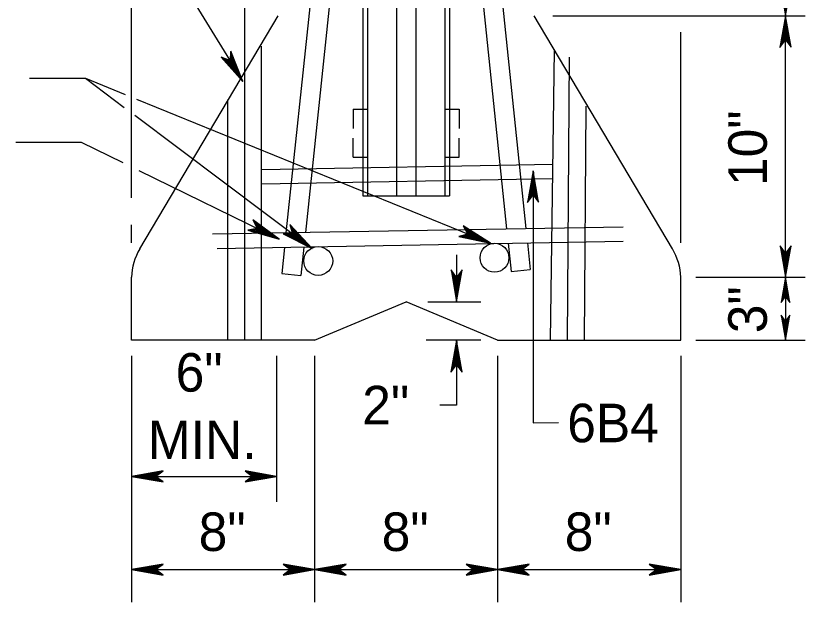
# Model space of a CAD drawing. Extents: x 499883 to 500983, y 499104 to 499764.
# Drawn here: x 500324 to 500405.9, y 499417.1 to 499478 of the extents above; entities that cross this region are included whole.
import ezdxf

# ---------------------------------------------------------------- set-up
doc = ezdxf.new("R2010")
doc.units = 0
for name, color, linetype in [('24', 7, 'Continuous'), ('5', 7, 'Continuous'), ('60', 7, 'Continuous')]:
    doc.layers.add(name, color=color, linetype=linetype)

msp = doc.modelspace()

# ---------------------------------------------------------------- linework, layer by layer
at = {"layer": '24'}
for points in [[(500403.264, 499481.232), (500403.834, 499477.975), (500403.828, 499478.192)], [(500403.834, 499477.975), (500404.412, 499481.249)], [(500403.834, 499477.975), (500403.255, 499474.701), (500403.834, 499475.483), (500404.403, 499474.718), (500403.834, 499477.975), (500403.84, 499477.758), (500403.298, 499474.793), (500403.841, 499475.544), (500404.359, 499474.85), (500403.85, 499477.64), (500403.834, 499477.531), (500403.382, 499474.992), (500403.84, 499475.561), (500404.285, 499474.975), (500403.833, 499477.481), (500403.85, 499477.373), (500403.449, 499475.152), (500403.833, 499475.584), (500404.233, 499475.144), (500403.85, 499477.057), (500403.85, 499476.872), (500403.532, 499475.317), (500403.824, 499475.62), (500404.15, 499475.294), (500403.834, 499476.839), (500403.824, 499476.664), (500403.623, 499475.495), (500403.85, 499475.72), (500404.074, 499475.476), (500403.834, 499476.503), (500403.817, 499476.338), (500403.683, 499475.636), (500403.841, 499475.752), (500404.016, 499475.561), (500403.833, 499476.253), (500403.725, 499475.795), (500403.85, 499475.861), (500403.975, 499475.66), (500403.85, 499476.138), (500403.775, 499475.837), (500403.874, 499475.963), (500403.933, 499475.819), (500403.841, 499475.962), (500403.824, 499475.887)], [(500377.672, 499461.885), (500377.063, 499458.617), (500377.649, 499459.394), (500378.212, 499458.623), (500377.672, 499461.885), (500377.676, 499461.668), (500377.107, 499458.708), (500377.657, 499459.455), (500378.168, 499458.756), (500377.685, 499461.551), (500377.668, 499461.441), (500377.193, 499458.906), (500377.657, 499459.471), (500378.096, 499458.882), (500377.667, 499461.392), (500377.683, 499461.283), (500377.262, 499459.066), (500377.65, 499459.495), (500378.045, 499459.05), (500377.68, 499460.967), (500377.678, 499460.782), (500377.346, 499459.23), (500377.641, 499459.53), (500377.964, 499459.201), (500377.662, 499460.749), (500377.65, 499460.574), (500377.439, 499459.407), (500377.668, 499459.63), (500377.89, 499459.384), (500377.659, 499460.414), (500377.641, 499460.249), (500377.5, 499459.548), (500377.659, 499459.662), (500377.832, 499459.469), (500377.656, 499460.163), (500377.543, 499459.707), (500377.669, 499459.771), (500377.792, 499459.569), (500377.672, 499460.048), (500377.594, 499459.748), (500377.694, 499459.873), (500377.751, 499459.728), (500377.661, 499459.873), (500377.643, 499459.797)], [(500377.672, 499461.885), (500377.646, 499435.755), (500380.277, 499435.775)], [(500403.834, 499450.84), (500404.412, 499454.114), (500403.834, 499453.332), (500403.264, 499454.097), (500403.834, 499450.84), (500403.828, 499451.058), (500404.37, 499454.022), (500403.827, 499453.271), (500403.309, 499453.965), (500403.818, 499451.175), (500403.834, 499451.284), (500404.285, 499453.824), (500403.827, 499453.254), (500403.383, 499453.84), (500403.834, 499451.334), (500403.818, 499451.443), (500404.218, 499453.663), (500403.834, 499453.231), (500403.434, 499453.672), (500403.817, 499451.759), (500403.818, 499451.943), (500404.136, 499453.498), (500403.843, 499453.196), (500403.517, 499453.521), (500403.834, 499451.977), (500403.844, 499452.151), (500404.044, 499453.32), (500403.817, 499453.095), (500403.593, 499453.339), (500403.834, 499452.312), (500403.85, 499452.477), (500403.985, 499453.179), (500403.827, 499453.063), (500403.652, 499453.254), (500403.834, 499452.563), (500403.943, 499453.02), (500403.818, 499452.954), (500403.692, 499453.155), (500403.817, 499452.678), (500403.892, 499452.978), (500403.794, 499452.852), (500403.735, 499452.997), (500403.827, 499452.853), (500403.843, 499452.928)], [(500403.834, 499450.84), (500403.371, 499448.221), (500403.834, 499448.847), (500404.29, 499448.235), (500403.834, 499450.84), (500403.838, 499450.666), (500403.405, 499448.295), (500403.839, 499448.896), (500404.253, 499448.34), (500403.847, 499450.573), (500403.834, 499450.485), (500403.472, 499448.454), (500403.839, 499448.909), (500404.195, 499448.441), (500403.833, 499450.445), (500403.847, 499450.358), (500403.526, 499448.583), (500403.833, 499448.928), (500404.153, 499448.575), (500403.847, 499450.106), (500403.847, 499449.958), (500403.592, 499448.714), (500403.826, 499448.956), (500404.086, 499448.695), (500403.834, 499449.931), (500403.826, 499449.792), (500403.666, 499448.856), (500403.847, 499449.036), (500404.026, 499448.841), (500403.834, 499449.663), (500403.82, 499449.531), (500403.713, 499448.969), (500403.839, 499449.062), (500403.979, 499448.909), (500403.833, 499449.463), (500403.746, 499449.096), (500403.847, 499449.149), (500403.947, 499448.989), (500403.847, 499449.37), (500403.787, 499449.13), (500403.866, 499449.231), (500403.913, 499449.115), (500403.839, 499449.23), (500403.826, 499449.17)], [(500403.834, 499444.305), (500404.297, 499446.924), (500403.834, 499446.298), (500403.378, 499446.91), (500403.834, 499444.305), (500403.829, 499444.479), (500404.263, 499446.85), (500403.828, 499446.249), (500403.414, 499446.805), (500403.821, 499444.572), (500403.834, 499444.66), (500404.195, 499446.691), (500403.828, 499446.236), (500403.473, 499446.704), (500403.834, 499444.699), (500403.821, 499444.786), (500404.141, 499446.563), (500403.834, 499446.217), (500403.515, 499446.57), (500403.82, 499445.039), (500403.821, 499445.187), (500404.076, 499446.431), (500403.841, 499446.189), (500403.581, 499446.449), (500403.834, 499445.213), (500403.842, 499445.353), (500404.002, 499446.288), (500403.82, 499446.108), (500403.641, 499446.304), (500403.834, 499445.482), (500403.847, 499445.614), (500403.954, 499446.175), (500403.828, 499446.083), (500403.688, 499446.236), (500403.834, 499445.682), (500403.921, 499446.049), (500403.821, 499445.996), (500403.72, 499446.156), (500403.82, 499445.774), (500403.881, 499446.015), (500403.802, 499445.914), (500403.754, 499446.03), (500403.828, 499445.915), (500403.841, 499445.975)], [(500336.003, 499430.184), (500339.277, 499429.605), (500338.495, 499430.184), (500339.261, 499430.753), (500336.003, 499430.184), (500336.221, 499430.189), (500339.186, 499429.648), (500338.434, 499430.191), (500339.128, 499430.709), (500336.338, 499430.2), (500336.447, 499430.184), (500338.987, 499429.732), (500338.417, 499430.19), (500339.003, 499430.635), (500336.497, 499430.183), (500336.606, 499430.2), (500338.826, 499429.799), (500338.394, 499430.183), (500338.835, 499430.583), (500336.922, 499430.2), (500337.107, 499430.2), (500338.661, 499429.882), (500338.359, 499430.174), (500338.684, 499430.5), (500337.14, 499430.184), (500337.314, 499430.173), (500338.483, 499429.973), (500338.259, 499430.2), (500338.502, 499430.424), (500337.475, 499430.184), (500337.64, 499430.167), (500338.342, 499430.033), (500338.226, 499430.191), (500338.418, 499430.366), (500337.725, 499430.183), (500338.183, 499430.075), (500338.117, 499430.2), (500338.318, 499430.325), (500337.841, 499430.2), (500338.141, 499430.125), (500338.015, 499430.224), (500338.16, 499430.283), (500338.016, 499430.191), (500338.091, 499430.174)], [(500351.043, 499430.184), (500347.769, 499430.762), (500348.551, 499430.184), (500347.786, 499429.614), (500351.043, 499430.184), (500350.826, 499430.178), (500347.861, 499430.719), (500348.612, 499430.177), (500347.918, 499429.659), (500350.708, 499430.167), (500350.599, 499430.184), (500348.059, 499430.635), (500348.629, 499430.177), (500348.043, 499429.732), (500350.549, 499430.184), (500350.44, 499430.167), (500348.22, 499430.568), (500348.652, 499430.184), (500348.211, 499429.784), (500350.124, 499430.167), (500349.94, 499430.167), (500348.385, 499430.486), (500348.687, 499430.193), (500348.362, 499429.868), (500349.907, 499430.184), (500349.732, 499430.194), (500348.563, 499430.394), (500348.788, 499430.167), (500348.544, 499429.943), (500349.571, 499430.184), (500349.406, 499430.2), (500348.704, 499430.334), (500348.82, 499430.177), (500348.629, 499430.002), (500349.321, 499430.184), (500348.863, 499430.293), (500348.929, 499430.167), (500348.728, 499430.042), (500349.205, 499430.167), (500348.905, 499430.242), (500349.031, 499430.144), (500348.887, 499430.084), (500349.03, 499430.177), (500348.955, 499430.193)], [(500336.003, 499420.505), (500339.277, 499419.926), (500338.495, 499420.505), (500339.261, 499421.075), (500336.003, 499420.505), (500336.221, 499420.511), (500339.186, 499419.969), (500338.434, 499420.512), (500339.128, 499421.03), (500336.338, 499420.521), (500336.447, 499420.505), (500338.987, 499420.053), (500338.417, 499420.512), (500339.003, 499420.956), (500336.497, 499420.504), (500336.606, 499420.521), (500338.826, 499420.12), (500338.394, 499420.504), (500338.835, 499420.904), (500336.922, 499420.521), (500337.107, 499420.521), (500338.661, 499420.203), (500338.359, 499420.496), (500338.684, 499420.821), (500337.14, 499420.505), (500337.314, 499420.495), (500338.483, 499420.295), (500338.259, 499420.521), (500338.502, 499420.746), (500337.475, 499420.505), (500337.64, 499420.488), (500338.342, 499420.354), (500338.226, 499420.512), (500338.418, 499420.687), (500337.725, 499420.504), (500338.183, 499420.396), (500338.117, 499420.521), (500338.318, 499420.646), (500337.841, 499420.521), (500338.141, 499420.446), (500338.015, 499420.545), (500338.16, 499420.604), (500338.016, 499420.512), (500338.091, 499420.496)], [(500354.989, 499420.505), (500351.715, 499421.084), (500352.497, 499420.505), (500351.732, 499419.935), (500354.989, 499420.505), (500354.771, 499420.499), (500351.807, 499421.041), (500352.558, 499420.498), (500351.864, 499419.98), (500354.654, 499420.489), (500354.545, 499420.505), (500352.005, 499420.957), (500352.575, 499420.498), (500351.989, 499420.054), (500354.495, 499420.505), (500354.387, 499420.489), (500352.166, 499420.89), (500352.598, 499420.505), (500352.157, 499420.106), (500354.07, 499420.488), (500353.886, 499420.489), (500352.331, 499420.807), (500352.633, 499420.514), (500352.308, 499420.189), (500353.853, 499420.505), (500353.678, 499420.515), (500352.509, 499420.715), (500352.734, 499420.488), (500352.49, 499420.264), (500353.517, 499420.505), (500353.352, 499420.521), (500352.65, 499420.656), (500352.766, 499420.498), (500352.575, 499420.323), (500353.267, 499420.505), (500352.809, 499420.614), (500352.875, 499420.489), (500352.674, 499420.363), (500353.151, 499420.488), (500352.851, 499420.563), (500352.977, 499420.465), (500352.832, 499420.406), (500352.976, 499420.498), (500352.901, 499420.514)], [(500354.989, 499420.505), (500358.263, 499419.926), (500357.481, 499420.505), (500358.246, 499421.075), (500354.989, 499420.505), (500355.206, 499420.511), (500358.171, 499419.969), (500357.42, 499420.512), (500358.114, 499421.03), (500355.324, 499420.521), (500355.433, 499420.505), (500357.972, 499420.053), (500357.403, 499420.512), (500357.989, 499420.956), (500355.483, 499420.504), (500355.591, 499420.521), (500357.811, 499420.12), (500357.379, 499420.504), (500357.82, 499420.904), (500355.907, 499420.521), (500356.092, 499420.521), (500357.647, 499420.203), (500357.344, 499420.496), (500357.67, 499420.821), (500356.125, 499420.505), (500356.3, 499420.495), (500357.469, 499420.295), (500357.244, 499420.521), (500357.488, 499420.746), (500356.46, 499420.505), (500356.625, 499420.488), (500357.328, 499420.354), (500357.212, 499420.512), (500357.403, 499420.687), (500356.711, 499420.504), (500357.169, 499420.396), (500357.103, 499420.521), (500357.304, 499420.646), (500356.826, 499420.521), (500357.127, 499420.446), (500357.001, 499420.545), (500357.145, 499420.604), (500357.001, 499420.512), (500357.077, 499420.496)], [(500373.974, 499420.505), (500370.7, 499421.084), (500371.483, 499420.505), (500370.717, 499419.935), (500373.974, 499420.505), (500373.757, 499420.499), (500370.792, 499421.041), (500371.544, 499420.498), (500370.849, 499419.98), (500373.64, 499420.489), (500373.531, 499420.505), (500370.991, 499420.957), (500371.56, 499420.498), (500370.975, 499420.054), (500373.481, 499420.505), (500373.372, 499420.489), (500371.152, 499420.89), (500371.584, 499420.505), (500371.143, 499420.106), (500373.056, 499420.488), (500372.871, 499420.489), (500371.316, 499420.807), (500371.619, 499420.514), (500371.293, 499420.189), (500372.838, 499420.505), (500372.663, 499420.515), (500371.495, 499420.715), (500371.719, 499420.488), (500371.475, 499420.264), (500372.503, 499420.505), (500372.338, 499420.521), (500371.636, 499420.656), (500371.751, 499420.498), (500371.56, 499420.323), (500372.252, 499420.505), (500371.794, 499420.614), (500371.861, 499420.489), (500371.66, 499420.363), (500372.137, 499420.488), (500371.836, 499420.563), (500371.962, 499420.465), (500371.818, 499420.406), (500371.962, 499420.498), (500371.887, 499420.514)], [(500373.974, 499420.505), (500377.248, 499419.926), (500376.466, 499420.505), (500377.231, 499421.075), (500373.974, 499420.505), (500374.192, 499420.511), (500377.157, 499419.969), (500376.405, 499420.512), (500377.099, 499421.03), (500374.309, 499420.521), (500374.418, 499420.505), (500376.958, 499420.053), (500376.388, 499420.512), (500376.974, 499420.956), (500374.468, 499420.504), (500374.577, 499420.521), (500376.797, 499420.12), (500376.365, 499420.504), (500376.806, 499420.904), (500374.893, 499420.521), (500375.078, 499420.521), (500376.632, 499420.203), (500376.33, 499420.496), (500376.655, 499420.821), (500375.111, 499420.505), (500375.285, 499420.495), (500376.454, 499420.295), (500376.229, 499420.521), (500376.473, 499420.746), (500375.446, 499420.505), (500375.611, 499420.488), (500376.313, 499420.354), (500376.197, 499420.512), (500376.389, 499420.687), (500375.696, 499420.504), (500376.154, 499420.396), (500376.088, 499420.521), (500376.289, 499420.646), (500375.812, 499420.521), (500376.112, 499420.446), (500375.986, 499420.545), (500376.131, 499420.604), (500375.987, 499420.512), (500376.062, 499420.496)], [(500392.96, 499420.505), (500389.686, 499421.084), (500390.468, 499420.505), (500389.703, 499419.935), (500392.96, 499420.505), (500392.743, 499420.499), (500389.778, 499421.041), (500390.529, 499420.498), (500389.835, 499419.98), (500392.625, 499420.489), (500392.516, 499420.505), (500389.977, 499420.957), (500390.546, 499420.498), (500389.96, 499420.054), (500392.466, 499420.505), (500392.358, 499420.489), (500390.138, 499420.89), (500390.57, 499420.505), (500390.129, 499420.106), (500392.042, 499420.488), (500391.857, 499420.489), (500390.302, 499420.807), (500390.605, 499420.514), (500390.279, 499420.189), (500391.824, 499420.505), (500391.649, 499420.515), (500390.48, 499420.715), (500390.705, 499420.488), (500390.461, 499420.264), (500391.489, 499420.505), (500391.324, 499420.521), (500390.621, 499420.656), (500390.737, 499420.498), (500390.546, 499420.323), (500391.238, 499420.505), (500390.78, 499420.614), (500390.846, 499420.489), (500390.645, 499420.363), (500391.123, 499420.488), (500390.822, 499420.563), (500390.948, 499420.465), (500390.804, 499420.406), (500390.948, 499420.498), (500390.872, 499420.514)]]:
    msp.add_lwpolyline(points, dxfattribs=at)
at = {"layer": '5'}
for p, q in [((500403.834, 499477.975), (500403.834, 499526.242)), ((500358.258, 499514.732), (500352.017, 499455.451)), ((500368.792, 499514.441), (500374.899, 499455.866)), ((500370.749, 499514.732), (500376.902, 499455.918)), ((500360.485, 499509.168), (500360.485, 499459.293)), ((500363.483, 499509.168), (500363.483, 499459.293)), ((500365.481, 499509.199), (500365.481, 499459.293)), ((500368.479, 499509.199), (500368.479, 499459.293)), ((500368.978, 499509.199), (500368.978, 499459.293)), ((500358.61, 499498.82), (500354.029, 499455.472)), ((500359.985, 499498.127), (500359.985, 499459.293)), ((500347.745, 499444.305), (500347.745, 499497.261)), ((500336.003, 499459.079), (500336.003, 499487.137)), ((500336.853, 499453.78), (500351.219, 499477.975)), ((500392.11, 499453.78), (500377.744, 499477.975)), ((500379.709, 499477.975), (500405.877, 499477.975)), ((500403.834, 499450.84), (500403.834, 499477.975)), ((500392.96, 499454.419), (500392.96, 499476.283)), ((500349.493, 499444.305), (500349.493, 499474.811)), ((500379.47, 499444.305), (500379.856, 499474.397)), ((500381.219, 499444.317), (500381.436, 499473.672)), ((500331.205, 499471.5), (500335.343, 499469.814)), ((500336.521, 499469.334), (500373.236, 499454.373)), ((500345.995, 499444.305), (500345.995, 499469.242)), ((500382.968, 499444.305), (500383.147, 499468.582)), ((500336.335, 499467.646), (500354.718, 499453.838)), ((500358.986, 499468.286), (500358.986, 499466.288)), ((500358.986, 499468.286), (500360.485, 499468.286)), ((500368.479, 499468.286), (500369.977, 499468.286)), ((500369.977, 499468.286), (500369.977, 499466.288)), ((500358.986, 499463.29), (500358.986, 499465.288)), ((500369.977, 499463.29), (500369.977, 499465.288)), ((500358.986, 499463.29), (500360.485, 499463.29)), ((500368.479, 499463.29), (500369.977, 499463.29)), ((500336.756, 499461.931), (500351.292, 499454.801)), ((500349.494, 499462.042), (500379.683, 499462.578)), ((500349.52, 499460.543), (500379.71, 499461.079)), ((500359.985, 499459.293), (500368.978, 499459.293)), ((500336.003, 499454.419), (500336.003, 499456.277)), ((500344.407, 499455.336), (500386.979, 499456.092)), ((500344.867, 499453.845), (500387.006, 499454.593)), ((500351.857, 499453.937), (500351.574, 499451.251)), ((500353.869, 499453.962), (500353.56, 499451.041)), ((500375.055, 499454.378), (500375.361, 499451.443)), ((500377.06, 499454.402), (500377.348, 499451.652)), ((500369.721, 499453.158), (500369.721, 499448.301)), ((500351.573, 499451.251), (500353.56, 499451.041)), ((500375.361, 499451.443), (500377.348, 499451.652)), ((500336.003, 499444.305), (500336.003, 499450.84)), ((500392.96, 499444.305), (500392.96, 499450.84)), ((500394.542, 499450.84), (500405.877, 499450.84)), ((500403.834, 499450.84), (500403.834, 499444.305)), ((500354.989, 499444.305), (500364.482, 499448.301)), ((500373.974, 499444.305), (500364.482, 499448.301)), ((500366.715, 499448.301), (500372.219, 499448.301)), ((500354.989, 499444.305), (500336.003, 499444.305)), ((500372.219, 499444.305), (500366.562, 499444.305)), ((500373.974, 499444.305), (500392.96, 499444.305)), ((500394.542, 499444.305), (500405.877, 499444.305)), ((500336.003, 499442.685), (500336.003, 499417.126)), ((500351.043, 499442.685), (500351.043, 499427.536)), ((500354.989, 499442.685), (500354.989, 499417.126)), ((500373.974, 499442.685), (500373.974, 499417.126)), ((500392.96, 499442.685), (500392.96, 499417.126)), ((500336.003, 499430.184), (500351.043, 499430.184)), ((500336.003, 499420.505), (500354.989, 499420.505)), ((500354.989, 499420.505), (500373.974, 499420.505)), ((500373.974, 499420.505), (500392.96, 499420.505))]:
    msp.add_line(p, q, dxfattribs=at)
for points in [[(500326.216, 499494.065), (500333.475, 499494.065), (500347.528, 499471.164)], [(500347.528, 499471.164), (500346.29, 499474.304), (500346.204, 499473.32), (500345.306, 499473.68), (500347.528, 499471.164), (500347.407, 499471.349), (500346.302, 499474.202), (500346.231, 499473.263), (500345.414, 499473.589), (500347.336, 499471.445), (500347.292, 499471.548), (500346.334, 499473.985), (500346.241, 499473.249), (500345.544, 499473.52), (500347.266, 499471.591), (500347.194, 499471.676), (500346.362, 499473.811), (500346.259, 499473.232), (500345.679, 499473.402), (500347.025, 499471.95), (500346.928, 499472.11), (500346.378, 499473.624), (500346.285, 499473.207), (500345.83, 499473.315), (500346.924, 499472.146), (500346.84, 499472.304), (500346.393, 499473.421), (500346.316, 499473.106), (500345.993, 499473.198), (500346.746, 499472.437), (500346.673, 499472.589), (500346.416, 499473.268), (500346.341, 499473.084), (500346.088, 499473.156), (500346.614, 499472.654), (500346.464, 499473.108), (500346.391, 499472.984), (500346.176, 499473.091), (500346.538, 499472.745), (500346.443, 499473.045), (500346.424, 499472.883), (500346.297, 499472.977), (500346.453, 499472.901), (500346.427, 499472.975)], [(500325.409, 499471.5), (500331.205, 499471.5), (500335.232, 499468.475)], [(500323.989, 499464.863), (500330.777, 499464.863), (500335.088, 499462.749)], [(500351.292, 499454.801), (500348.567, 499456.792), (500349.021, 499455.915), (500348.069, 499455.738), (500351.292, 499454.801), (500351.091, 499454.893), (500348.631, 499456.712), (500349.074, 499455.881), (500348.209, 499455.72), (500350.98, 499454.936), (500350.888, 499455), (500348.774, 499456.547), (500349.089, 499455.874), (500348.356, 499455.731), (500350.842, 499455.022), (500350.736, 499455.056), (500348.891, 499456.414), (500349.113, 499455.87), (500348.533, 499455.703), (500350.448, 499455.197), (500350.279, 499455.28), (500349.005, 499456.265), (500349.149, 499455.863), (500348.707, 499455.711), (500350.257, 499455.309), (500350.101, 499455.396), (500349.125, 499456.102), (500349.229, 499455.794), (500348.907, 499455.699), (500349.951, 499455.459), (500349.808, 499455.548), (500349.228, 499455.984), (500349.263, 499455.788), (500349.01, 499455.715), (500349.723, 499455.571), (500349.354, 499455.875), (500349.358, 499455.731), (500349.119, 499455.707), (500349.61, 499455.607), (500349.37, 499455.811), (500349.44, 499455.664), (500349.282, 499455.675), (500349.454, 499455.695), (500349.393, 499455.743)], [(500354.718, 499453.838), (500352.413, 499456.304), (500352.695, 499455.357), (500351.726, 499455.362), (500354.718, 499453.838), (500354.537, 499453.965), (500352.461, 499456.213), (500352.74, 499455.314), (500351.861, 499455.317), (500354.436, 499454.029), (500354.357, 499454.108), (500352.571, 499456.023), (500352.754, 499455.304), (500352.007, 499455.301), (500354.317, 499454.139), (500354.219, 499454.192), (500352.661, 499455.871), (500352.777, 499455.296), (500352.176, 499455.24), (500353.962, 499454.384), (500353.812, 499454.498), (500352.745, 499455.704), (500352.811, 499455.282), (500352.348, 499455.216), (500353.795, 499454.53), (500353.659, 499454.646), (500352.832, 499455.521), (500352.877, 499455.199), (500352.542, 499455.166), (500353.523, 499454.735), (500353.399, 499454.849), (500352.911, 499455.386), (500352.909, 499455.188), (500352.647, 499455.162), (500353.32, 499454.888), (500353.015, 499455.255), (500352.992, 499455.114), (500352.752, 499455.134), (500353.216, 499454.945), (500353.018, 499455.189), (500353.06, 499455.032), (500352.907, 499455.072), (500353.08, 499455.059), (500353.028, 499455.118)], [(500373.236, 499454.373), (500370.38, 499456.171), (500370.893, 499455.328), (500369.956, 499455.085), (500373.236, 499454.373), (500373.029, 499454.451), (500370.45, 499456.096), (500370.948, 499455.297), (500370.097, 499455.077), (500372.915, 499454.486), (500372.819, 499454.543), (500370.604, 499455.94), (500370.964, 499455.292), (500370.243, 499455.098), (500372.772, 499454.563), (500372.664, 499454.589), (500370.73, 499455.816), (500370.989, 499455.289), (500370.421, 499455.083), (500372.366, 499454.709), (500372.193, 499454.78), (500370.853, 499455.675), (500371.025, 499455.284), (500370.594, 499455.103), (500372.168, 499454.809), (500372.007, 499454.885), (500370.985, 499455.521), (500371.109, 499455.221), (500370.795, 499455.104), (500371.853, 499454.937), (500371.704, 499455.016), (500371.095, 499455.411), (500371.143, 499455.218), (500370.897, 499455.127), (500371.617, 499455.033), (500371.229, 499455.311), (500371.243, 499455.167), (500371.006, 499455.126), (500371.502, 499455.061), (500371.249, 499455.247), (500371.329, 499455.106), (500371.171, 499455.106), (500371.341, 499455.138), (500371.277, 499455.182)], [(500369.721, 499448.301), (500370.308, 499451.625), (500369.721, 499450.831), (500369.142, 499451.608), (500369.721, 499448.301), (500369.715, 499448.522), (500370.265, 499451.532), (500369.714, 499450.769), (500369.188, 499451.474), (500369.704, 499448.641), (500369.721, 499448.752), (500370.179, 499451.331), (500369.714, 499450.752), (500369.263, 499451.347), (500369.721, 499448.803), (500369.704, 499448.913), (500370.111, 499451.167), (500369.721, 499450.729), (500369.316, 499451.176), (500369.704, 499449.234), (500369.704, 499449.421), (500370.027, 499451), (500369.73, 499450.693), (500369.4, 499451.023), (500369.721, 499449.455), (500369.731, 499449.632), (500369.934, 499450.819), (500369.704, 499450.591), (500369.477, 499450.838), (500369.721, 499449.795), (500369.738, 499449.963), (500369.874, 499450.675), (500369.714, 499450.558), (500369.536, 499450.752), (500369.721, 499450.05), (500369.831, 499450.514), (500369.704, 499450.447), (500369.577, 499450.651), (500369.704, 499450.167), (500369.781, 499450.472), (500369.68, 499450.344), (500369.62, 499450.49), (500369.714, 499450.345), (500369.73, 499450.421)], [(500369.721, 499444.305), (500369.721, 499437.58), (500367.973, 499437.58)], [(500369.721, 499444.305), (500369.133, 499440.98), (500369.721, 499441.774), (500370.299, 499440.998), (500369.721, 499444.305), (500369.727, 499444.084), (500369.177, 499441.074), (500369.728, 499441.837), (500370.254, 499441.132), (500369.737, 499443.964), (500369.721, 499443.854), (500369.263, 499441.275), (500369.728, 499441.854), (500370.179, 499441.259), (500369.721, 499443.803), (500369.737, 499443.693), (500369.33, 499441.439), (500369.721, 499441.877), (500370.126, 499441.43), (500369.738, 499443.372), (500369.738, 499443.184), (500369.414, 499441.606), (500369.712, 499441.913), (500370.042, 499441.583), (500369.721, 499443.151), (500369.71, 499442.973), (500369.507, 499441.786), (500369.738, 499442.015), (500369.965, 499441.768), (500369.721, 499442.81), (500369.704, 499442.643), (500369.568, 499441.93), (500369.728, 499442.047), (500369.905, 499441.853), (500369.72, 499442.556), (500369.611, 499442.091), (500369.738, 499442.158), (500369.865, 499441.955), (500369.738, 499442.439), (500369.661, 499442.134), (500369.762, 499442.262), (500369.822, 499442.115), (500369.728, 499442.261), (500369.712, 499442.185)]]:
    msp.add_lwpolyline(points, dxfattribs=at)
for centre, start, end in [((500341.985, 499450.679), 148.85817, 178.45857), ((500386.978, 499450.679), 1.54143, 31.14183)]:
    msp.add_arc(centre, 5.995, start, end, dxfattribs=at)
at = {"layer": '60'}
for centre in [(500355.36, 499452.533), (500373.647, 499452.866)]:
    msp.add_circle(centre, 1.499, dxfattribs=at)

# ---------------------------------------------------------------- texts
at = {"layer": '5'}
for s, p in [('10"', (500401.897, 499460.307)), ('3"', (500401.897, 499445.037))]:
    msp.add_text(s, height=4, rotation=90, dxfattribs=at).set_placement(p)
for s, p in [('6"', (500340.568, 499438.976)), ('2"', (500359.924, 499435.58)), ('6B4', (500381.189, 499433.722)), ('MIN.', (500337.678, 499431.976)), ('8"', (500342.961, 499422.442)), ('8"', (500361.946, 499422.442)), ('8"', (500380.932, 499422.442))]:
    msp.add_text(s, height=4, dxfattribs=at).set_placement(p)

doc.saveas('drawing.dxf')
